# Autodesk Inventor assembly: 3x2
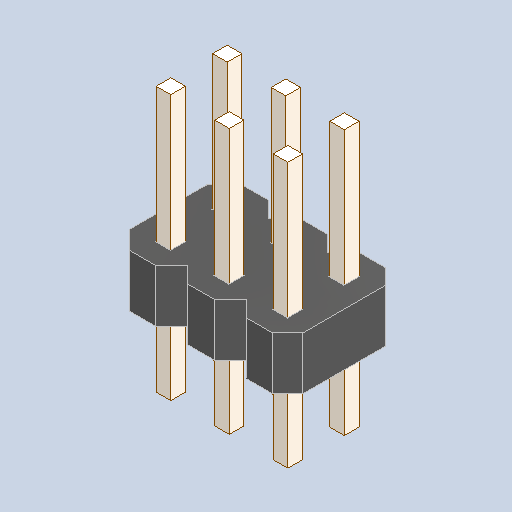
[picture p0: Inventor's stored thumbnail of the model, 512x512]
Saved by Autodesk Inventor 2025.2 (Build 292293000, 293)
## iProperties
Created: 2025-04
Part Number: 3x2
Description: PART--DESC
Document SubType Name: Assembly
Designer: BennF
Author: BennF
Revision Number: NONE
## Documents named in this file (3)
- C:\Users\BennF\Nextcloud\Benutzer\CNC JarBeRi\existing parts\Electronics\RepRap A4988 Shied (USE WITHOUT ARDUINO)\reprap-a4988-1.snapshot.1\RepRap\RepRap\3x2_3.iam
- C:\Users\BennF\Nextcloud\Benutzer\CNC JarBeRi\existing parts\Electronics\RepRap A4988 Shied (USE WITHOUT ARDUINO)\reprap-a4988-1.snapshot.1\RepRap\RepRap\3x2 Geometry.ipt
- C:\Users\BennF\Nextcloud\Benutzer\CNC JarBeRi\existing parts\Electronics\RepRap A4988 Shied (USE WITHOUT ARDUINO)\reprap-a4988-1.snapshot.1\RepRap\RepRap\pin10.ipt
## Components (2 placed, 2 different names)
1. 3x2 Geometry
2. pin10
